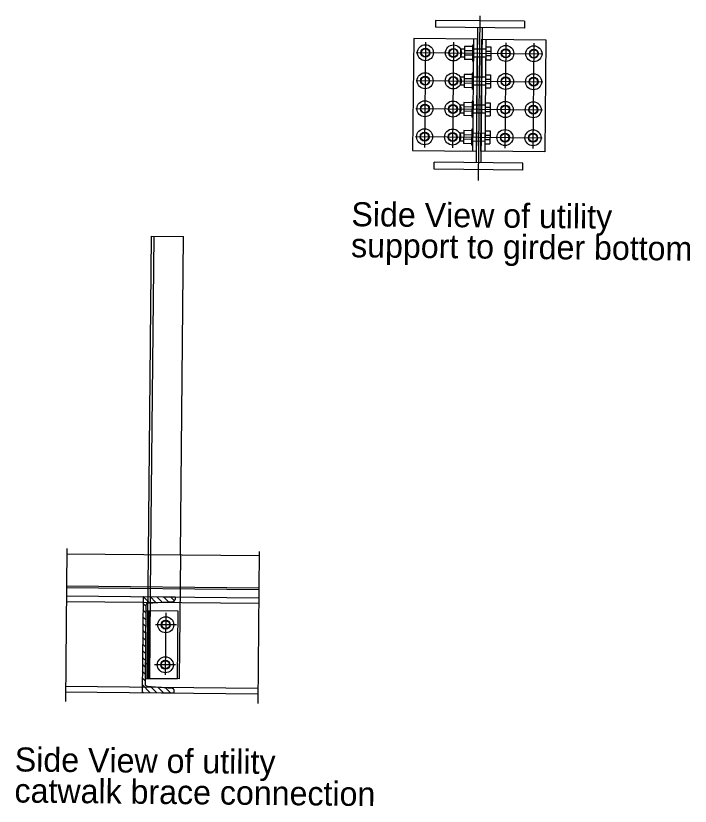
# Model space of a CAD drawing. Extents: x 632312 to 632885, y 378199 to 378534.
# Drawn here: x 632384.03 to 632391.05, y 378380.21 to 378388.43 of the extents above; entities that cross this region are included whole.
import ezdxf

# ---------------------------------------------------------------- set-up
doc = ezdxf.new("R2010")
doc.units = 0
for name, color, linetype in [('B_Boring', 7, 'Continuous'), ('R_Proposed Const Limits Cut', 7, 'Continuous'), ('R_Wall', 7, 'Continuous'), ('SHT_Dimensions', 7, 'Continuous'), ('USACE_Easement', 7, 'Continuous')]:
    doc.layers.add(name, color=color, linetype=linetype)

msp = doc.modelspace()

# ---------------------------------------------------------------- linework, layer by layer
at = {"layer": 'B_Boring'}
for p, q in [((632388.398, 378388.3842), (632388.3973, 378388.3117)), ((632389.323, 378388.375), (632388.398, 378388.3842)), ((632389.323, 378388.375), (632389.3223, 378388.3025)), ((632389.3223, 378388.3025), (632388.3973, 378388.3117)), ((632388.8235, 378386.9024), (632388.8375, 378388.3073)), ((632388.8821, 378388.3069), (632388.8681, 378386.9019)), ((632388.1711, 378388.1948), (632388.1595, 378387.0282)), ((632388.8363, 378388.1882), (632388.1711, 378388.1948)), ((632388.7836, 378388.1262), (632388.7819, 378387.9595)), ((632388.7946, 378388.1886), (632388.783, 378387.022)), ((632388.794, 378388.1261), (632388.7836, 378388.1262)), ((632388.794, 378388.1261), (632388.7924, 378387.9594)), ((632388.8247, 378387.0215), (632388.8363, 378388.1882)), ((632388.8693, 378387.0211), (632388.8809, 378388.1877)), ((632388.8809, 378388.1877), (632389.5461, 378388.1811)), ((632388.9226, 378388.1873), (632388.911, 378387.0207)), ((632389.5461, 378388.1811), (632389.5345, 378387.0145)), ((632388.6582, 378388.0858), (632388.6574, 378388.0024)), ((632388.6999, 378388.0853), (632388.6582, 378388.0858)), ((632388.7001, 378388.1114), (632388.6988, 378387.976)), ((632388.783, 378388.0654), (632388.6997, 378388.0662)), ((632388.7834, 378388.1105), (632388.7001, 378388.1114)), ((632388.9218, 378388.1092), (632388.9204, 378387.9738)), ((632388.9213, 378388.064), (632388.9734, 378388.0635)), ((632388.9218, 378388.1092), (632388.9739, 378388.1086)), ((632388.9739, 378388.1086), (632388.9725, 378387.9733)), ((632388.699, 378388.002), (632388.6574, 378388.0024)), ((632388.7821, 378387.9751), (632388.6988, 378387.976)), ((632388.7825, 378388.0203), (632388.6992, 378388.0211)), ((632388.7924, 378387.9594), (632388.7819, 378387.9595)), ((632388.9204, 378387.9738), (632388.9725, 378387.9733)), ((632388.9209, 378388.0189), (632388.973, 378388.0184)), ((632388.6553, 378387.7941), (632388.6545, 378387.7108)), ((632388.697, 378387.7937), (632388.6553, 378387.7941)), ((632388.6972, 378387.8197), (632388.6959, 378387.6843)), ((632388.7805, 378387.8189), (632388.6972, 378387.8197)), ((632388.7807, 378387.8345), (632388.779, 378387.6679)), ((632388.7911, 378387.8344), (632388.7807, 378387.8345)), ((632388.7911, 378387.8344), (632388.7895, 378387.6678)), ((632388.9189, 378387.8175), (632388.9175, 378387.6821)), ((632388.9189, 378387.8175), (632388.971, 378387.817)), ((632388.971, 378387.817), (632388.9696, 378387.6816)), ((632388.6961, 378387.7104), (632388.6545, 378387.7108)), ((632388.7796, 378387.7286), (632388.6963, 378387.7295)), ((632388.7801, 378387.7738), (632388.6968, 378387.7746)), ((632388.918, 378387.7272), (632388.9701, 378387.7267)), ((632388.9184, 378387.7724), (632388.9705, 378387.7719)), ((632388.7792, 378387.6835), (632388.6959, 378387.6843)), ((632388.7895, 378387.6678), (632388.779, 378387.6679)), ((632388.9175, 378387.6821), (632388.9696, 378387.6816)), ((632388.7778, 378387.5429), (632388.7761, 378387.3762)), ((632388.7882, 378387.5428), (632388.7778, 378387.5429)), ((632388.7882, 378387.5428), (632388.7866, 378387.3761)), ((632388.6524, 378387.5024), (632388.6516, 378387.4191)), ((632388.6941, 378387.502), (632388.6524, 378387.5024)), ((632388.6943, 378387.5281), (632388.693, 378387.3927)), ((632388.7772, 378387.4821), (632388.6939, 378387.4829)), ((632388.7776, 378387.5272), (632388.6943, 378387.5281)), ((632388.916, 378387.5259), (632388.9146, 378387.3905)), ((632388.9155, 378387.4807), (632388.9676, 378387.4802)), ((632388.916, 378387.5259), (632388.9681, 378387.5253)), ((632388.9681, 378387.5253), (632388.9667, 378387.3899)), ((632388.6932, 378387.4187), (632388.6516, 378387.4191)), ((632388.7763, 378387.3918), (632388.693, 378387.3927)), ((632388.7767, 378387.437), (632388.6934, 378387.4378)), ((632388.7866, 378387.3761), (632388.7761, 378387.3762)), ((632388.9146, 378387.3905), (632388.9667, 378387.3899)), ((632388.9151, 378387.4356), (632388.9672, 378387.4351)), ((632388.6495, 378387.2108), (632388.6487, 378387.1275)), ((632388.6912, 378387.2104), (632388.6495, 378387.2108)), ((632388.6914, 378387.2364), (632388.6901, 378387.101)), ((632388.7747, 378387.2356), (632388.6914, 378387.2364)), ((632388.7749, 378387.2512), (632388.7732, 378387.0846)), ((632388.7853, 378387.2511), (632388.7749, 378387.2512)), ((632388.7853, 378387.2511), (632388.7837, 378387.0845)), ((632388.9131, 378387.2342), (632388.9117, 378387.0988)), ((632388.9131, 378387.2342), (632388.9652, 378387.2337)), ((632388.9652, 378387.2337), (632388.9638, 378387.0983)), ((632388.6903, 378387.1271), (632388.6487, 378387.1275)), ((632388.7738, 378387.1453), (632388.6905, 378387.1461)), ((632388.7743, 378387.1905), (632388.691, 378387.1913)), ((632388.9122, 378387.1439), (632388.9643, 378387.1434)), ((632388.9126, 378387.1891), (632388.9647, 378387.1886)), ((632388.7734, 378387.1002), (632388.6901, 378387.101)), ((632388.7837, 378387.0845), (632388.7732, 378387.0846)), ((632388.9117, 378387.0988), (632388.9638, 378387.0983)), ((632388.1595, 378387.0282), (632388.8247, 378387.0215)), ((632389.5345, 378387.0145), (632388.8693, 378387.0211)), ((632388.3826, 378386.8343), (632388.3833, 378386.9068)), ((632389.3083, 378386.8976), (632388.3833, 378386.9068)), ((632389.3076, 378386.8251), (632389.3083, 378386.8976)), ((632389.3076, 378386.8251), (632388.3826, 378386.8343)), ((632385.4113, 378382.8247), (632385.4442, 378386.137)), ((632385.4442, 378386.137), (632385.7775, 378386.1337)), ((632385.7446, 378382.8214), (632385.7775, 378386.1337)), ((632384.5637, 378382.8331), (632386.5636, 378382.8132)), ((632386.56, 378382.4591), (632384.5601, 378382.479)), ((632384.5603, 378382.4998), (632386.5602, 378382.4799)), ((632384.5593, 378382.3956), (632386.5592, 378382.3758)), ((632385.3553, 378382.3877), (632385.3453, 378381.3878)), ((632385.3553, 378382.3877), (632385.6886, 378382.3844)), ((632385.4244, 378382.3198), (632385.3577, 378382.3877)), ((632385.4899, 378382.3243), (632385.4285, 378382.387)), ((632385.5554, 378382.3289), (632385.4992, 378382.3863)), ((632385.621, 378382.3335), (632385.5699, 378382.3856)), ((632385.682, 378382.3426), (632385.6406, 378382.3849)), ((632385.6886, 378382.3844), (632385.6883, 378382.3573)), ((632384.5587, 378382.3373), (632386.5586, 378382.3174)), ((632385.3851, 378382.2884), (632385.3546, 378382.3195)), ((632385.3852, 378382.2979), (632385.3771, 378381.477)), ((632385.4063, 378382.3185), (632385.6673, 378382.3367)), ((632385.3844, 378382.2177), (632385.3539, 378382.2488)), ((632385.3847, 378382.2416), (632385.718, 378382.2383)), ((632385.4159, 378382.2413), (632385.4089, 378381.533)), ((632385.718, 378382.2383), (632385.7109, 378381.53)), ((632385.3837, 378382.1469), (632385.3532, 378382.1781)), ((632385.3823, 378382.0055), (632385.3518, 378382.0367)), ((632385.383, 378382.0762), (632385.3525, 378382.1074)), ((632385.3816, 378381.9348), (632385.3511, 378381.966)), ((632385.3809, 378381.8641), (632385.3504, 378381.8953)), ((632385.3802, 378381.7934), (632385.3497, 378381.8246)), ((632385.3795, 378381.7227), (632385.349, 378381.7538)), ((632385.3788, 378381.652), (632385.3483, 378381.6831)), ((632385.3774, 378381.5106), (632385.3469, 378381.5417)), ((632385.3781, 378381.5813), (632385.3476, 378381.6124)), ((632385.3776, 378381.5333), (632385.7109, 378381.53)), ((632384.5499, 378381.454), (632386.5498, 378381.4341)), ((632385.4286, 378381.387), (632385.3462, 378381.471)), ((632385.3977, 378381.456), (632385.6583, 378381.4326)), ((632385.4993, 378381.3863), (632385.4341, 378381.4528)), ((632384.5461, 378381.3957), (632386.5493, 378381.3758)), ((632385.3453, 378381.3878), (632385.6787, 378381.3845)), ((632385.3453, 378381.3878), (632385.6786, 378381.3845)), ((632385.3485, 378381.3878), (632385.3454, 378381.3909)), ((632385.3579, 378381.3877), (632385.3455, 378381.4003)), ((632385.57, 378381.3856), (632385.5109, 378381.4459)), ((632385.6407, 378381.3849), (632385.5876, 378381.439)), ((632385.6779, 378381.4183), (632385.6651, 378381.4314)), ((632385.6787, 378381.3845), (632385.6789, 378381.4116))]:
    msp.add_line(p, q, dxfattribs=at)
for centre in [(632388.2932, 378388.0477), (632388.5849, 378388.0448), (632389.1294, 378388.0396), (632389.4211, 378388.0367), (632388.2903, 378387.7561), (632388.582, 378387.7532), (632389.1265, 378387.748), (632389.4182, 378387.7451), (632388.2874, 378387.4644), (632388.5791, 378387.4615), (632389.1236, 378387.4563), (632389.4153, 378387.4534), (632388.2845, 378387.1728), (632388.5762, 378387.1699), (632389.1207, 378387.1646), (632389.4124, 378387.1617), (632385.5915, 378382.0937), (632385.5874, 378381.6771)]:
    msp.add_circle(centre, 0.0469, dxfattribs=at)
for centre, start, end in [((632385.6675, 378382.3575), 269.43036, 359.43882), ((632385.406, 378382.2977), 89.43036, 179.43036), ((632385.3979, 378381.4768), 179.43036, 269.43036), ((632385.6581, 378381.4118), 359.43036, 89.43036)]:
    msp.add_arc(centre, 0.0208, start, end, dxfattribs=at)
at = {"layer": 'R_Proposed Const Limits Cut'}
for p, q in [((632388.9215, 378388.0831), (632388.7936, 378388.0844)), ((632388.9207, 378387.9998), (632388.7928, 378388.0011)), ((632388.9186, 378387.7915), (632388.7907, 378387.7928)), ((632388.9178, 378387.7082), (632388.7899, 378387.7094)), ((632388.9157, 378387.4998), (632388.7878, 378387.5011)), ((632388.9149, 378387.4165), (632388.787, 378387.4178)), ((632388.9128, 378387.2082), (632388.7849, 378387.2094)), ((632388.912, 378387.1248), (632388.7841, 378387.1261)), ((632385.4373, 378382.8244), (632385.4703, 378386.1368)), ((632385.3985, 378381.5331), (632385.4113, 378382.8247)), ((632385.4245, 378381.5328), (632385.4373, 378382.8244)), ((632385.7446, 378382.8214), (632385.7318, 378381.5298)), ((632385.7318, 378381.5298), (632385.3985, 378381.5331))]:
    msp.add_line(p, q, dxfattribs=at)
for centre, radius in [((632388.2932, 378388.0477), 0.0833), ((632388.5849, 378388.0448), 0.0833), ((632389.1294, 378388.0396), 0.0833), ((632389.4211, 378388.0367), 0.0833), ((632388.2932, 378388.0477), 0.0417), ((632388.5849, 378388.0448), 0.0417), ((632389.1294, 378388.0396), 0.0417), ((632389.4211, 378388.0367), 0.0417), ((632388.2903, 378387.7561), 0.0833), ((632388.2903, 378387.7561), 0.0417), ((632388.582, 378387.7532), 0.0833), ((632388.582, 378387.7532), 0.0417), ((632389.1265, 378387.748), 0.0833), ((632389.1265, 378387.748), 0.0417), ((632389.4182, 378387.7451), 0.0833), ((632389.4182, 378387.7451), 0.0417), ((632388.2874, 378387.4644), 0.0833), ((632388.5791, 378387.4615), 0.0833), ((632389.1236, 378387.4563), 0.0833), ((632388.2874, 378387.4644), 0.0417), ((632388.5791, 378387.4615), 0.0417), ((632389.1236, 378387.4563), 0.0417), ((632389.4153, 378387.4534), 0.0833), ((632389.4153, 378387.4534), 0.0417), ((632388.2845, 378387.1728), 0.0833), ((632388.2845, 378387.1728), 0.0417), ((632388.5762, 378387.1699), 0.0833), ((632388.5762, 378387.1699), 0.0417), ((632389.1207, 378387.1646), 0.0833), ((632389.4124, 378387.1617), 0.0833), ((632389.1207, 378387.1646), 0.0417), ((632389.4124, 378387.1617), 0.0417), ((632385.5915, 378382.0937), 0.0833), ((632385.5915, 378382.0937), 0.0417), ((632385.5874, 378381.6771), 0.0833), ((632385.5874, 378381.6771), 0.0417)]:
    msp.add_circle(centre, radius, dxfattribs=at)
at = {"layer": 'R_Wall'}
for p, q in [((632388.844, 378386.717), (632388.861, 378388.4314)), ((632388.2943, 378388.1587), (632388.2834, 378387.0617)), ((632388.586, 378388.1558), (632388.5751, 378387.0588)), ((632389.1305, 378388.1506), (632389.1196, 378387.0536)), ((632389.4222, 378388.1477), (632389.4113, 378387.0507)), ((632388.1984, 378388.0487), (632389.5159, 378388.0356)), ((632388.1955, 378387.757), (632389.513, 378387.7439)), ((632388.1926, 378387.4654), (632389.5101, 378387.4523)), ((632388.1897, 378387.1737), (632389.5072, 378387.1606)), ((632385.5928, 378382.2165), (632385.5863, 378381.5714)), ((632385.7023, 378382.0926), (632385.4852, 378382.0948)), ((632385.692, 378381.676), (632385.4743, 378381.6782))]:
    msp.add_line(p, q, dxfattribs=at)
at = {"layer": 'SHT_Dimensions'}
for p, q in [((632384.5642, 378382.8861), (632384.5484, 378381.2952)), ((632386.564, 378382.8565), (632386.5483, 378381.2753)), ((632385.3847, 378382.2416), (632385.3776, 378381.5333))]:
    msp.add_line(p, q, dxfattribs=at)

# ---------------------------------------------------------------- texts
at = {"layer": 'USACE_Easement'}
for s, p in [('Side View of utility ', (632387.5222, 378386.2423)), ('support to girder bottom', (632387.519, 378385.9188)), ('Side View of utility ', (632384.0204, 378380.5678)), ('catwalk brace connection', (632384.0172, 378380.2443))]:
    msp.add_text(s, height=0.25, rotation=359.43036, dxfattribs=at).set_placement(p)

doc.saveas('drawing.dxf')
